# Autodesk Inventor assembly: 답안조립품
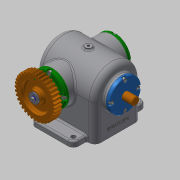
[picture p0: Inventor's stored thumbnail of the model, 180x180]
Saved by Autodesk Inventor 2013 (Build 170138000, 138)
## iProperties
Created: 2019-05
Part Number: 답안조립품
Document SubType Name: Assembly
Designer: Administrator
Mass: 1342.39 g
Surface Area: 1805.89 cm^2
Volume: 591.154 cm^3
Density: 2.27079 g/cm^3
Author: Administrator
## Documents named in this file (16)
- C:\Users\Administrator\Desktop\390504V1046\답안조립품.iam
- C:\Users\Administrator\Desktop\390504V1046\본체.ipt
- C:\Users\Administrator\Desktop\390504V1046\가변스프링.ipt
- C:\Users\Administrator\Desktop\390504V1046\가이드부시.ipt
- C:\Users\Administrator\Desktop\390504V1046\베어링 6203.ipt
- C:\Users\Administrator\Desktop\390504V1046\볼트 M4x8.ipt
- C:\Users\Administrator\Desktop\390504V1046\볼트 M4x10.ipt
- C:\Users\Administrator\Desktop\390504V1046\스퍼기어.ipt
- C:\Users\Administrator\Desktop\390504V1046\스프링와셔.ipt
- C:\Users\Administrator\Desktop\390504V1046\슬라이더.ipt
- C:\Users\Administrator\Desktop\390504V1046\오일 실 17 32 8.ipt
- C:\Users\Administrator\Desktop\390504V1046\커버 A.ipt
- C:\Users\Administrator\Desktop\390504V1046\커버 B.ipt
- C:\Users\Administrator\Desktop\390504V1046\키 4x4x14.ipt
- C:\Users\Administrator\Desktop\390504V1046\편심축.ipt
- C:\Users\Administrator\Desktop\390504V1046\평와셔.ipt
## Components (2 placed, 2 different names)
1. 가변스프링:1
2. 가이드부시:1
